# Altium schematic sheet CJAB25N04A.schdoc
size 127 x 101 mm
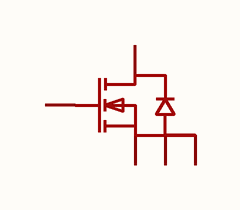
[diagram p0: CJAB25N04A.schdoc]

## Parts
Q?  cjab25n04a  [PDFN3333-8_L3.1-W3.2-P0.65-LS3.4-BL_1]  (value not drawn)

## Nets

Not connected (* = marked no-connect by the designer): Q? 1(S) 2(S) 3(S) 4(G) 5(D)

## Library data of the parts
Q? = cjab25n04a: 数量:1个N沟道;漏源电压(Vdss):40V;连续漏极电流(Id):25A;导通电阻(RDS(on)):8.4mΩ@4.5V;耗散功率(Pd):50W;阈值电压(Vgs(th)):2.5V;; Manufacturer: CJ(江苏长电/长晶); AddInBom: yes; ModelId: c288237aeb774e1d92142cc9eea176d4; ModelTransform: 118.8974,118.8974,0,90,0,0,0,19.486,0; Number: 1个N沟道; Drain to Source Voltage: 40V; Current - Continuous Drain(Id): 25A; Pd - Power Dissipation: 50W; Gate Threshold Voltage (Vgs(th)): 2.5V; Gate Charge(Qg): 60nC@10V; Input Capacitance(Ciss): 2.893nF; Reverse Transfer Capacitance (Crss@Vds): 154pF; Type: N沟道; Output Capacitance(Coss): 189pF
